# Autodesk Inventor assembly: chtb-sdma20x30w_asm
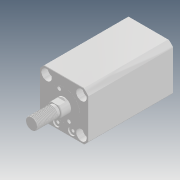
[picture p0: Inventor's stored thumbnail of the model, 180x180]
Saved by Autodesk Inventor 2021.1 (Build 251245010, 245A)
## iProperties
Company: Microsoft
Created: 2018-05
Part Number: chtb-sdma20x30w_asm
Description: STEP AP214
Document SubType Name: Assembly
Designer: user
Title: chtb-sdma20x30w_asm.STEP
Author: Windows
Revision Number: ÈÎºÎ
Sending System: SolidWorks 2015
Preprocessor: SwSTEP 2.0
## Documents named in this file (4)
- D:\Vault_2016\Projekty\Clamptek\Hydraulic\CHTB\CHTB-20\Inventor\CHTB-SDMA20x30W\chtb-sdma20x30w_asm.iam
- D:\Vault_2016\Projekty\Clamptek\Hydraulic\CHTB\CHTB-20\Inventor\CHTB-SDMA20x30W\CHTB-SDMA20X30NBT.ipt
- D:\Vault_2016\Projekty\Clamptek\Hydraulic\CHTB\CHTB-20\Inventor\CHTB-SDMA20x30W\CHTB-SDMA20X30WHSG.ipt
- D:\Vault_2016\Projekty\Clamptek\Hydraulic\CHTB\CHTB-20\Inventor\CHTB-SDMA20x30W\QG_3.ipt
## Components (3 placed, 3 different names)
1. CHTB-SDMA20X30NBT_1
2. CHTB-SDMA20X30WHSG_2
3. QG_3_3
